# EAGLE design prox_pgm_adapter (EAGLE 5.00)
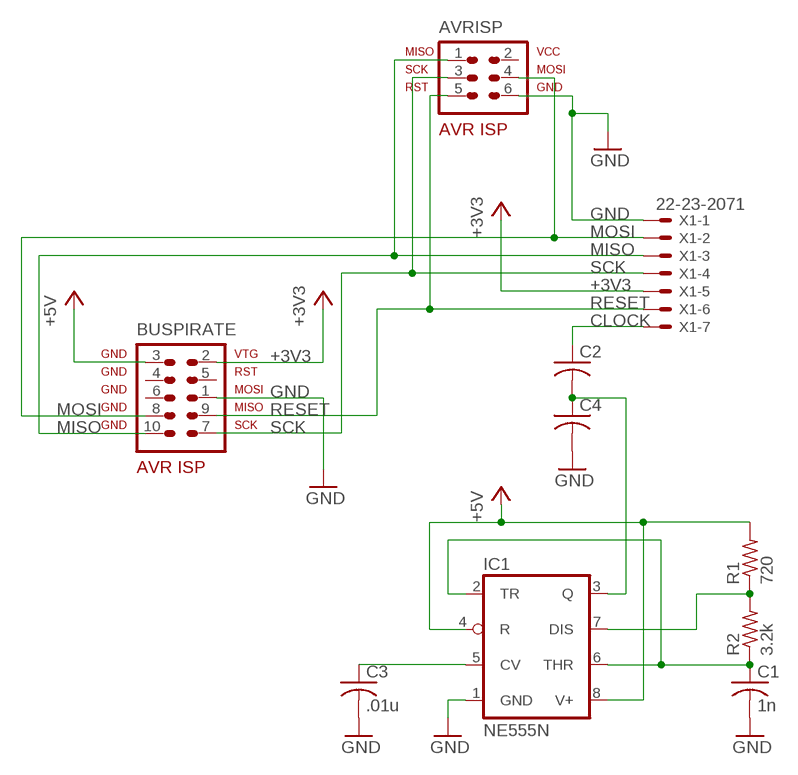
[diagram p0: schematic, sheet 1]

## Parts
AVRISP  AVR-ISP-6VERT  [AVR-ISP-6]
BUSPIRATE  BusPirate  AVR-ISP-10  [AVR-ISP-10]
C1  1n  C-US050-025X075  [C050-025X075]
C2  C-US050-025X075  [C050-025X075]
C3  .01u  C-US050-025X075  [C050-025X075]
C4  C-US050-025X075  [C050-025X075]
IC1  NE555N  [DIL08]
R1  720  R-US_0207/7  [0207/7]
R2  3.2k  R-US_0207/7  [0207/7]
X1  22-23-2071  [22-23-2071]

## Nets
+3V3: BUSPIRATE.2 X1.5
+5V: BUSPIRATE.3 IC1.4(R) IC1.8(V+) R1.2
CLOCK: C2.2 C4.1 IC1.3(Q)
GND: AVRISP.6 BUSPIRATE.1 C1.2 C3.2 C4.2 IC1.1(GND) X1.1
MISO: AVRISP.1 BUSPIRATE.10 X1.3
MOSI: AVRISP.4 BUSPIRATE.8 X1.2
N$1: IC1.7(DIS) R1.1 R2.2
N$2: C1.1 IC1.2(TR) IC1.6(THR) R2.1
N$3: C3.1 IC1.5(CV)
N$4: C2.1 X1.7
RESET: AVRISP.5 BUSPIRATE.9 X1.6
SCK: AVRISP.3 BUSPIRATE.7 X1.4
Unconnected: AVRISP.2 BUSPIRATE.4 BUSPIRATE.5 BUSPIRATE.6

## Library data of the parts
AVRISP = avr-7:AVR-ISP-6: AVR ISP-6 Serial Programming Header
BUSPIRATE = avr-7:AVR-ISP-10: AVR ISP-10 Serial Programming Header
C1-C4 = rcl:C-US: CAPACITOR, American symbol
IC1 = linear:*555: TIMER
R1 R2 = rcl:R-US_: RESISTOR, American symbol
X1 = con-molex:22-23-2071: .100" (2.54mm) Center Header - 7 Pin

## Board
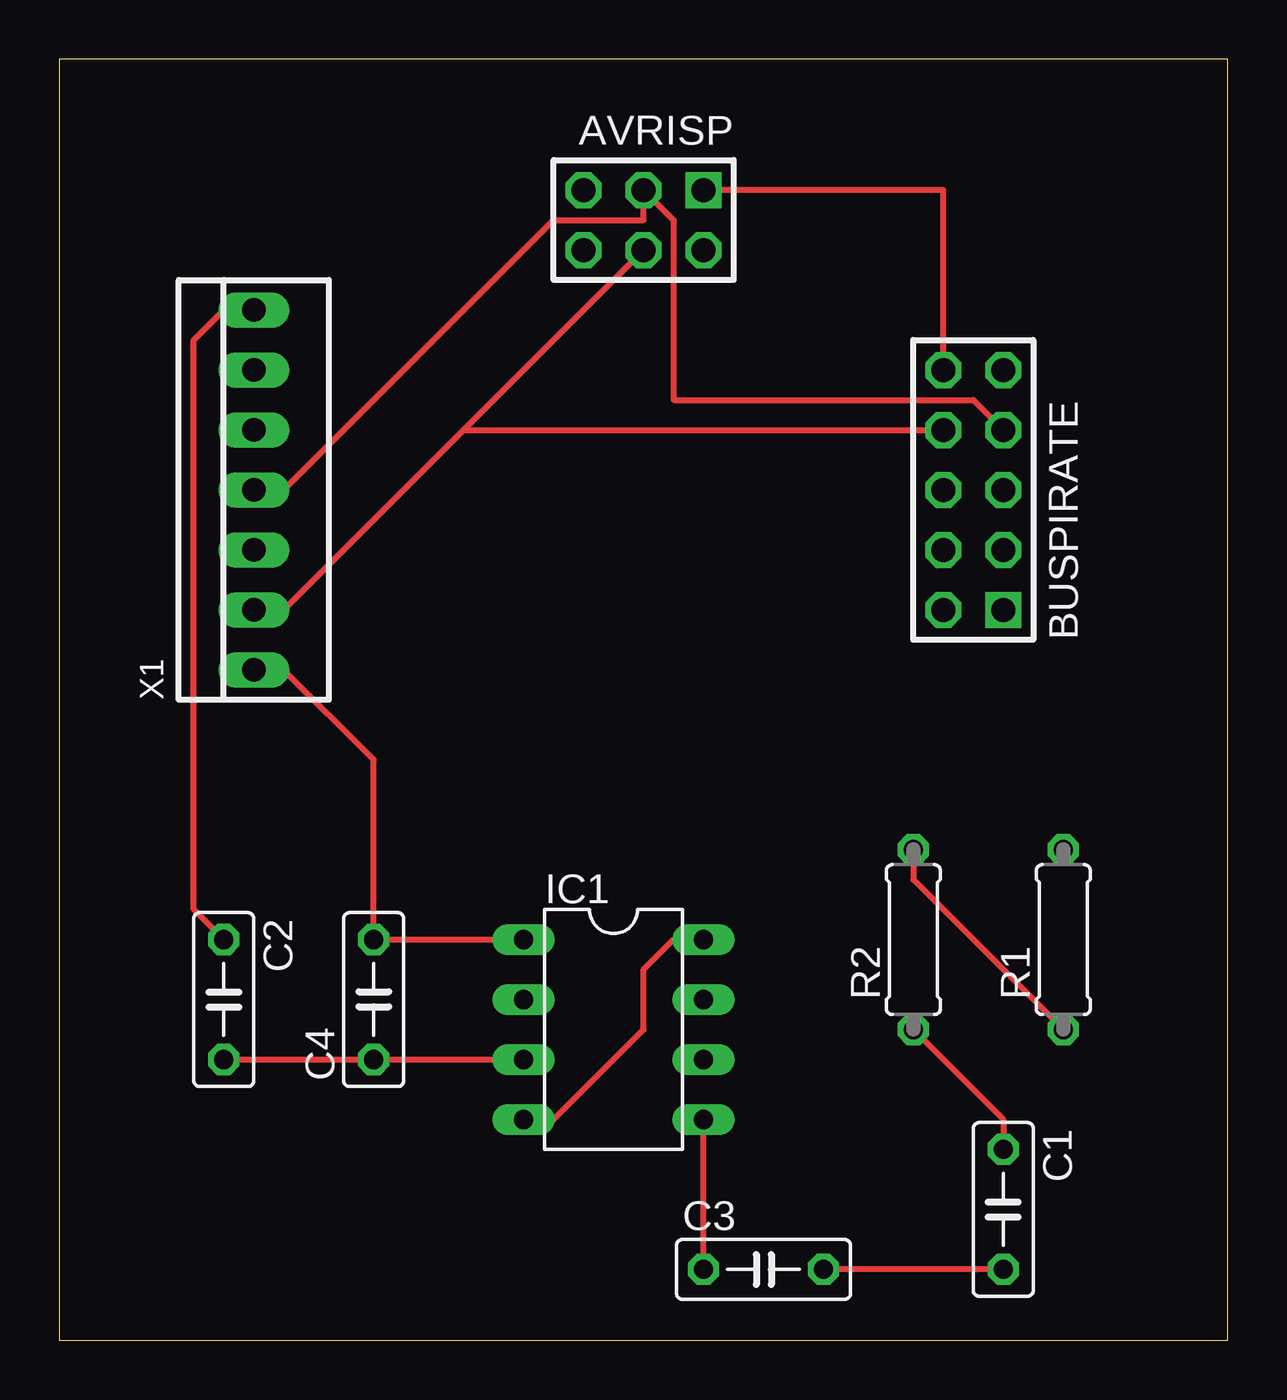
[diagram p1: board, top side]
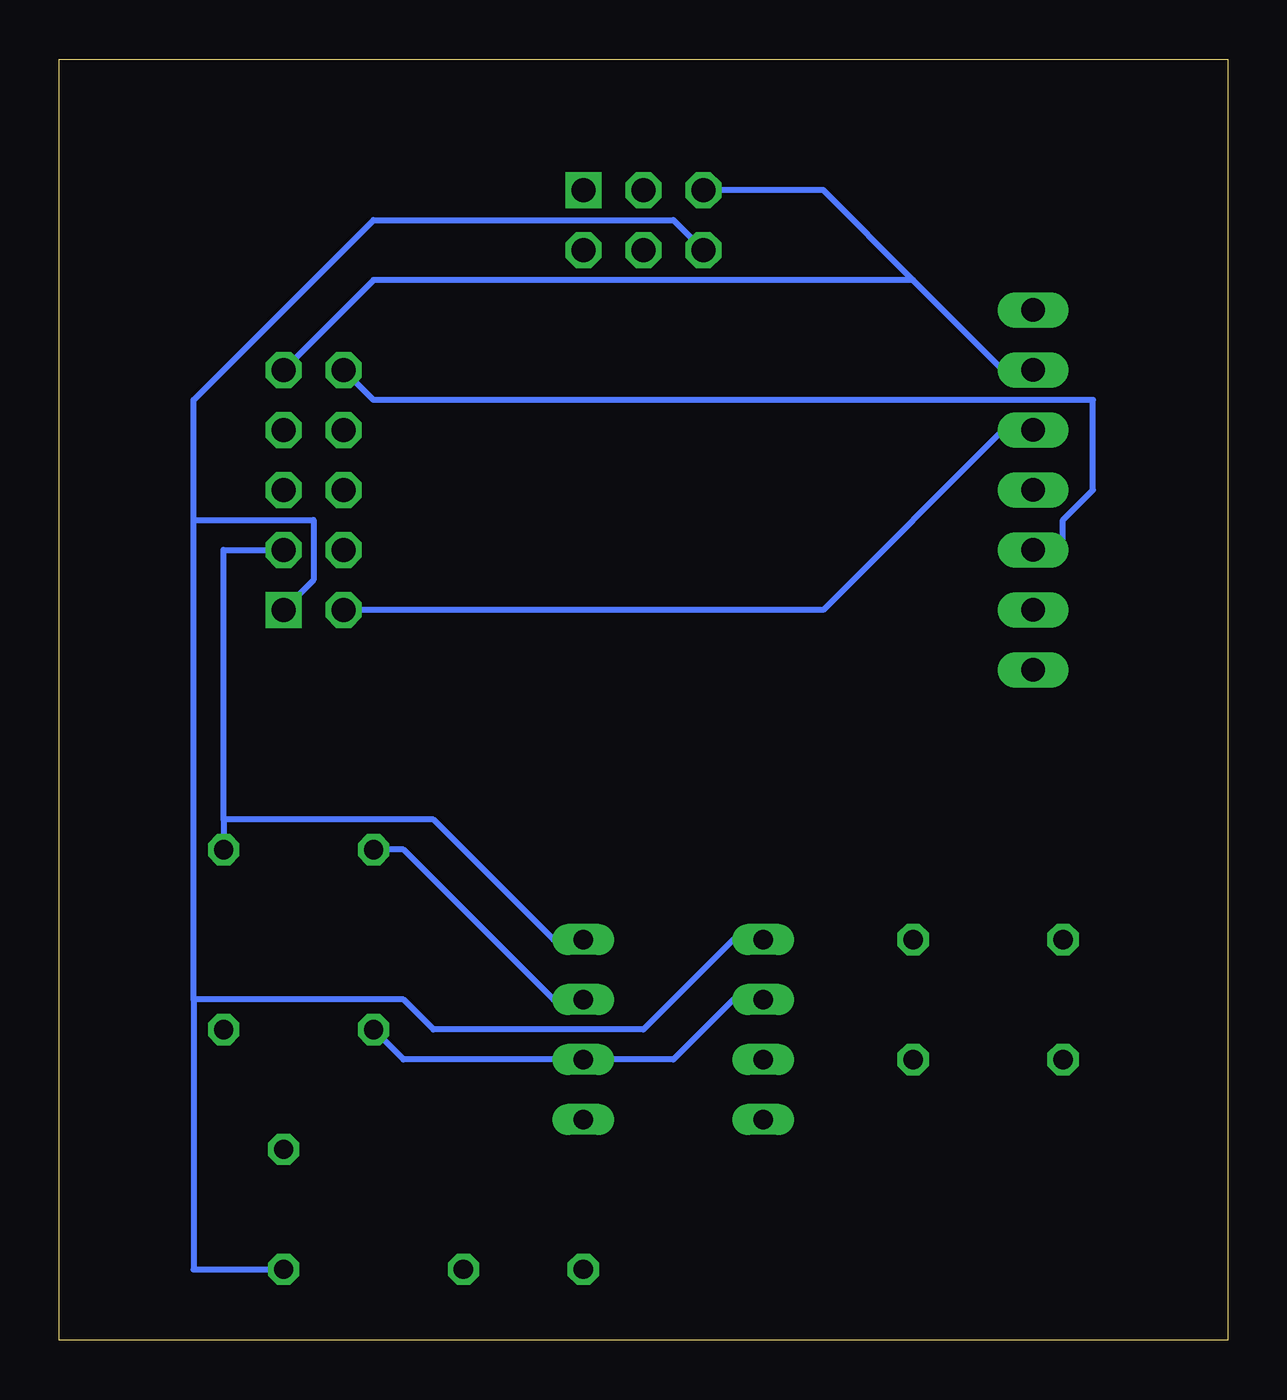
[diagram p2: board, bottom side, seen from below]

Size 49.51 x 54.28 mm. Coordinates in mm from the lower left corner, seen from the top.
Outline: 0,0 49.51,0 49.51,54.28 0,54.28 0,0
Copper layers (1*16): Top 0.035mm / dielectric 1.5mm / Bottom 0.035mm
Design rules "default": minimum track width 10mil, minimum drill 24mil, track to track 8mil, track to pad 8mil, pad to pad 8mil, via to via 8mil, smd to smd 8mil, copper to edge 40mil, drill to drill 8mil, minimum pad ring 10mil, minimum via ring 8mil, stop-mask expansion 4mil, vias tented up to drill 0mil, thermal gap 10mil

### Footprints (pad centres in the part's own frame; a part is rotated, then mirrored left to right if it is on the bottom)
AVR-ISP-6 = drill 1.016 square: 1 -2.54,-1.27 | drill 1.016 octagon: 2 -2.54,1.27; 3 0,-1.27; 4 0,1.27; 5 2.54,-1.27; 6 2.54,1.27
AVR-ISP-10 = drill 1.016 square: 1 -5.08,-1.27 | drill 1.016 octagon: 2 -5.08,1.27; 3 -2.54,-1.27; 4 -2.54,1.27; 5 0,-1.27; 6 0,1.27; 7 2.54,-1.27; 8 2.54,1.27; 9 5.08,-1.27; 10 5.08,1.27
C050-025X075 = drill 0.813 octagon: 1 -2.54,0; 2 2.54,0
DIL08 = drill 0.813 long: 1 -3.81,-3.81; 2 -1.27,-3.81; 3 1.27,-3.81; 4 3.81,-3.81; 5 3.81,3.81; 6 1.27,3.81; 7 -1.27,3.81; 8 -3.81,3.81
0207/7 = drill 0.813 octagon: 1 -3.81,0; 2 3.81,0
22-23-2071 = drill 1 long: 1 -7.62,0; 2 -5.08,0; 3 -2.54,0; 4 0,0; 5 2.54,0; 6 5.08,0; 7 7.62,0

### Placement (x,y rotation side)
AVRISP  24.76,47.46 180 top
BUSPIRATE  38.73,36.03 90 top
C1  40,5.55 270 top
C2  6.98,14.44 270 top
C3  29.84,3.01 0 top
C4  13.33,14.44 90 top
IC1  23.49,13.17 270 top
R1  42.54,16.98 90 top
R2  36.19,16.98 90 top
X1  8.25,36.03 90 top

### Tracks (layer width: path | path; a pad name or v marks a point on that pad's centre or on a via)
+3V3
  Bottom 0.254: BUSPIRATE.2 17.14,30.95 9.52,38.57 X1.5
+5V
  Top 0.254: IC1.4 20.95,9.36 24.76,13.17 24.76,15.71 26.03,16.98 IC1.8
  Bottom 0.254: 42.54,22.06 42.54,33.49 BUSPIRATE.3 | 42.54,22.06 R1.2 | 42.54,22.06 33.65,22.06 28.57,16.98 IC1.8
CLOCK
  Top 0.254: C2.2 C4.1 IC1.3
GND
  Top 0.254: IC1.1 C4.2 13.33,24.6 9.52,28.41 X1.1 | C1.2 C3.2
  Bottom 0.254: AVRISP.6 23.49,47.46 36.19,47.46 43.81,39.84 43.81,34.76 | 43.81,14.44 43.81,3.01 C1.2 | 43.81,14.44 43.81,34.76 | BUSPIRATE.1 38.73,32.22 38.73,34.76 43.81,34.76 | 43.81,14.44 34.92,14.44 33.65,13.17 24.76,13.17 20.95,16.98 IC1.1
MISO
  Top 0.254: AVRISP.1 37.46,48.73 BUSPIRATE.10
  Bottom 0.254: BUSPIRATE.10 36.19,39.84 5.71,39.84 5.71,36.03 6.98,34.76 6.98,33.49 X1.3
MOSI
  Top 0.254: 17.14,38.57 AVRISP.4 | 17.14,38.57 9.52,30.95 X1.2 | 17.14,38.57 BUSPIRATE.8
N$1
  Top 0.254: R1.1 36.19,19.52 R2.2
  Bottom 0.254: R2.2 34.92,20.79 28.57,14.44 IC1.7
N$2
  Top 0.254: R2.1 40,9.36 C1.1
  Bottom 0.254: IC1.2 20.95,14.44 23.49,11.9 IC1.6 34.92,11.9 R2.1
N$3
  Top 0.254: C3.1 IC1.5
N$4
  Top 0.254: C2.1 5.71,18.25 5.71,42.38 6.98,43.65 X1.7
RESET
  Bottom 0.254: 13.33,44.92 17.14,48.73 AVRISP.5 | 13.33,44.92 9.52,41.11 X1.6 | BUSPIRATE.9 36.19,44.92 13.33,44.92
SCK
  Top 0.254: X1.4 9.52,36.03 20.95,47.46 24.76,47.46 AVRISP.3 26.03,47.46 26.03,39.84 38.73,39.84 BUSPIRATE.7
